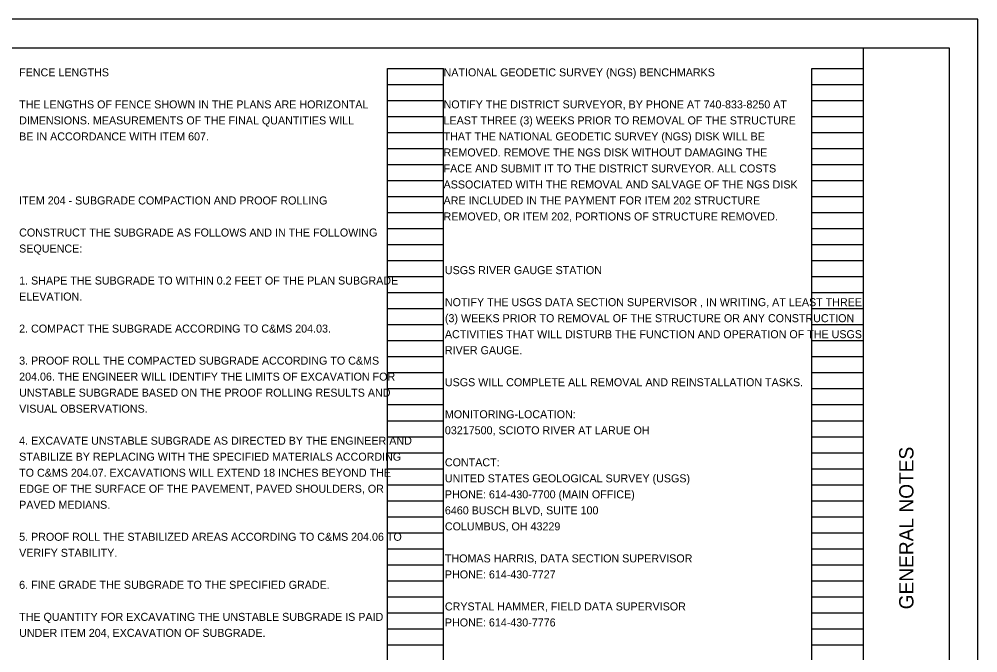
# Model space of a CAD drawing. Extents: x 0 to 34, y 0 to 22.
# Drawn here: x 17.24 to 34, y 10.92 to 22 of the extents above; entities that cross this region are included whole.
import ezdxf

# ---------------------------------------------------------------- set-up
doc = ezdxf.new("R2010")
doc.units = 0
for name, color, linetype in [('SH_Border', 7, 'Continuous'), ('SH_Cut_Line', 7, 'Continuous'), ('SH_Data', 7, 'Continuous'), ('SH_Text', 7, 'Continuous')]:
    doc.layers.add(name, color=color, linetype=linetype)

msp = doc.modelspace()

# ---------------------------------------------------------------- linework, layer by layer
at = {"layer": 'SH_Border'}
msp.add_line((32, 0.5), (32, 21.5), dxfattribs=at)
msp.add_lwpolyline([(1.5, 21.5), (33.5, 21.5), (33.5, 0.5), (1.5, 0.5)], close=True, dxfattribs=at)
at = {"layer": 'SH_Cut_Line'}
msp.add_lwpolyline([(0, 0), (34, 0), (34, 22), (0, 22)], close=True, dxfattribs=at)
at = {"layer": 'SH_Data'}
for p, q in [((23.68, 0.98), (23.68, 21.14)), ((23.68, 21.14), (24.66, 21.14)), ((24.66, 0.98), (24.66, 21.14)), ((31.1, 0.98), (31.1, 21.14)), ((31.1, 21.14), (32, 21.14)), ((32, 0.98), (32, 21.14)), ((23.68, 20.86), (24.66, 20.86)), ((31.1, 20.86), (32, 20.86)), ((23.68, 20.58), (24.66, 20.58)), ((31.1, 20.58), (32, 20.58)), ((23.68, 20.3), (24.66, 20.3)), ((31.1, 20.3), (32, 20.3)), ((23.68, 20.02), (24.66, 20.02)), ((31.1, 20.02), (32, 20.02)), ((23.68, 19.74), (24.66, 19.74)), ((31.1, 19.74), (32, 19.74)), ((23.68, 19.46), (24.66, 19.46)), ((31.1, 19.46), (32, 19.46)), ((23.68, 19.18), (24.66, 19.18)), ((31.1, 19.18), (32, 19.18)), ((23.68, 18.9), (24.66, 18.9)), ((31.1, 18.9), (32, 18.9)), ((23.68, 18.62), (24.66, 18.62)), ((31.1, 18.62), (32, 18.62)), ((23.68, 18.34), (24.66, 18.34)), ((31.1, 18.34), (32, 18.34)), ((23.68, 18.06), (24.66, 18.06)), ((31.1, 18.06), (32, 18.06)), ((23.68, 17.78), (24.66, 17.78)), ((31.1, 17.78), (32, 17.78)), ((23.68, 17.5), (24.66, 17.5)), ((31.1, 17.5), (32, 17.5)), ((23.68, 17.22), (24.66, 17.22)), ((31.1, 17.22), (32, 17.22)), ((23.68, 16.94), (24.66, 16.94)), ((31.1, 16.94), (32, 16.94)), ((23.68, 16.66), (24.66, 16.66)), ((31.1, 16.66), (32, 16.66)), ((23.68, 16.38), (24.66, 16.38)), ((31.1, 16.38), (32, 16.38)), ((23.68, 16.1), (24.66, 16.1)), ((31.1, 16.1), (32, 16.1)), ((23.68, 15.82), (24.66, 15.82)), ((31.1, 15.82), (32, 15.82)), ((23.68, 15.54), (24.66, 15.54)), ((31.1, 15.54), (32, 15.54)), ((23.68, 15.26), (24.66, 15.26)), ((31.1, 15.26), (32, 15.26)), ((23.68, 14.98), (24.66, 14.98)), ((31.1, 14.98), (32, 14.98)), ((23.68, 14.7), (24.66, 14.7)), ((31.1, 14.7), (32, 14.7)), ((23.68, 14.42), (24.66, 14.42)), ((31.1, 14.42), (32, 14.42)), ((23.68, 14.14), (24.66, 14.14)), ((31.1, 14.14), (32, 14.14)), ((23.68, 13.86), (24.66, 13.86)), ((31.1, 13.86), (32, 13.86)), ((23.68, 13.58), (24.66, 13.58)), ((31.1, 13.58), (32, 13.58)), ((23.68, 13.3), (24.66, 13.3)), ((31.1, 13.3), (32, 13.3)), ((23.68, 13.02), (24.66, 13.02)), ((31.1, 13.02), (32, 13.02)), ((23.68, 12.74), (24.66, 12.74)), ((31.1, 12.74), (32, 12.74)), ((23.68, 12.46), (24.66, 12.46)), ((31.1, 12.46), (32, 12.46)), ((23.68, 12.18), (24.66, 12.18)), ((31.1, 12.18), (32, 12.18)), ((23.68, 11.9), (24.66, 11.9)), ((31.1, 11.9), (32, 11.9)), ((23.68, 11.62), (24.66, 11.62)), ((31.1, 11.62), (32, 11.62)), ((23.68, 11.34), (24.66, 11.34)), ((31.1, 11.34), (32, 11.34)), ((23.68, 11.06), (24.66, 11.06)), ((31.1, 11.06), (32, 11.06))]:
    msp.add_line(p, q, dxfattribs=at)

# ---------------------------------------------------------------- texts
msp.add_text('GENERAL NOTES', height=0.25, rotation=90, dxfattribs=at).set_placement((32.875, 11.682))
at = {"layer": 'SH_Text'}
for s, p in [('FENCE LENGTHS', (17.24, 21)), ('NATIONAL GEODETIC SURVEY (NGS) BENCHMARKS', (24.66, 21)), ('THE LENGTHS OF FENCE SHOWN IN THE PLANS ARE HORIZONTAL', (17.24, 20.44)), ('NOTIFY THE DISTRICT SURVEYOR, BY PHONE AT 740-833-8250 AT', (24.66, 20.44)), ('DIMENSIONS. MEASUREMENTS OF THE FINAL QUANTITIES WILL', (17.24, 20.16)), ('LEAST THREE (3) WEEKS PRIOR TO REMOVAL OF THE STRUCTURE', (24.66, 20.16)), ('BE IN ACCORDANCE WITH ITEM 607.', (17.24, 19.88)), ('THAT THE NATIONAL GEODETIC SURVEY (NGS) DISK WILL BE', (24.66, 19.88)), ('REMOVED. REMOVE THE NGS DISK WITHOUT DAMAGING THE', (24.66, 19.6)), ('FACE AND SUBMIT IT TO THE DISTRICT SURVEYOR. ALL COSTS', (24.66, 19.32)), ('ASSOCIATED WITH THE REMOVAL AND SALVAGE OF THE NGS DISK', (24.66, 19.04)), ('ITEM 204 - SUBGRADE COMPACTION AND PROOF ROLLING', (17.24, 18.76)), ('ARE INCLUDED IN THE PAYMENT FOR ITEM 202 STRUCTURE', (24.66, 18.76)), ('REMOVED, OR ITEM 202, PORTIONS OF STRUCTURE REMOVED.', (24.66, 18.48)), ('CONSTRUCT THE SUBGRADE AS FOLLOWS AND IN THE FOLLOWING ', (17.24, 18.2)), ('SEQUENCE:', (17.24, 17.92)), ('USGS RIVER GAUGE STATION', (24.683, 17.542)), ('1. SHAPE THE SUBGRADE TO WITHIN 0.2 FEET OF THE PLAN SUBGRADE ', (17.24, 17.36)), ('ELEVATION.', (17.24, 17.08)), ('NOTIFY THE USGS DATA SECTION SUPERVISOR , IN WRITING, AT LEAST THREE ', (24.683, 16.982)), ('(3) WEEKS PRIOR TO REMOVAL OF THE STRUCTURE OR ANY CONSTRUCTION ', (24.683, 16.702)), ('2. COMPACT THE SUBGRADE ACCORDING TO C&MS 204.03.', (17.24, 16.52)), ('ACTIVITIES THAT WILL DISTURB THE FUNCTION AND OPERATION OF THE USGS ', (24.683, 16.422)), ('RIVER GAUGE.', (24.683, 16.142)), ('3. PROOF ROLL THE COMPACTED SUBGRADE ACCORDING TO C&MS ', (17.24, 15.96)), ('204.06. THE ENGINEER WILL IDENTIFY THE LIMITS OF EXCAVATION FOR ', (17.24, 15.68)), ('USGS WILL COMPLETE ALL REMOVAL AND REINSTALLATION TASKS.', (24.683, 15.582)), ('UNSTABLE SUBGRADE BASED ON THE PROOF ROLLING RESULTS AND ', (17.24, 15.4)), ('VISUAL OBSERVATIONS.', (17.24, 15.12)), ('MONITORING-LOCATION:', (24.683, 15.022)), ('03217500, SCIOTO RIVER AT LARUE OH', (24.683, 14.742)), ('4. EXCAVATE UNSTABLE SUBGRADE AS DIRECTED BY THE ENGINEER AND ', (17.24, 14.56)), ('STABILIZE BY REPLACING WITH THE SPECIFIED MATERIALS ACCORDING ', (17.24, 14.28)), ('CONTACT:', (24.683, 14.182)), ('TO C&MS 204.07. EXCAVATIONS WILL EXTEND 18 INCHES BEYOND THE ', (17.24, 14)), ('UNITED STATES GEOLOGICAL SURVEY (USGS)', (24.683, 13.902)), ('EDGE OF THE SURFACE OF THE PAVEMENT, PAVED SHOULDERS, OR ', (17.24, 13.72)), ('PHONE: 614-430-7700 (MAIN OFFICE)', (24.683, 13.622)), ('PAVED MEDIANS.', (17.24, 13.44)), ('6460 BUSCH BLVD, SUITE 100', (24.683, 13.342)), ('COLUMBUS, OH 43229', (24.683, 13.062)), ('5. PROOF ROLL THE STABILIZED AREAS ACCORDING TO C&MS 204.06 TO ', (17.24, 12.88)), ('VERIFY STABILITY.', (17.24, 12.6)), ('THOMAS HARRIS, DATA SECTION SUPERVISOR', (24.683, 12.502)), ('PHONE: 614-430-7727', (24.683, 12.222)), ('6. FINE GRADE THE SUBGRADE TO THE SPECIFIED GRADE.', (17.24, 12.04)), ('CRYSTAL HAMMER, FIELD DATA SUPERVISOR', (24.683, 11.662)), ('THE QUANTITY FOR EXCAVATING THE UNSTABLE SUBGRADE IS PAID ', (17.24, 11.48)), ('PHONE: 614-430-7776', (24.683, 11.382)), ('UNDER ITEM 204, EXCAVATION OF SUBGRADE.', (17.24, 11.2))]:
    msp.add_text(s, height=0.14, dxfattribs=at).set_placement(p)

doc.saveas('drawing.dxf')
